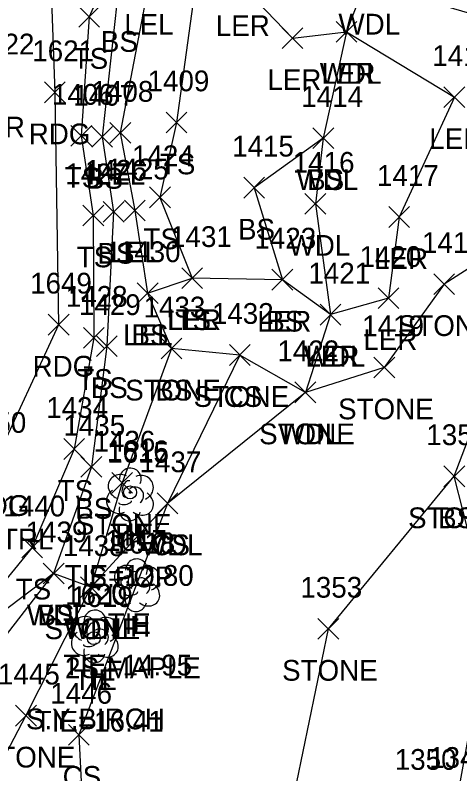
# Model space of a CAD drawing. Extents: x 1512665 to 1513714, y 110636 to 112816.
# Drawn here: x 1513122.1 to 1513164.9, y 110778.5 to 110851.6 of the extents above; entities that cross this region are included whole.
import ezdxf

# ---------------------------------------------------------------- set-up
doc = ezdxf.new("R2010")
doc.units = 0
for name, color, linetype in [('C_A', 7, 'Continuous'), ('C_C', 7, 'Continuous'), ('C_I', 7, 'Continuous'), ('CBP', 7, 'Continuous'), ('L_A', 7, 'Continuous'), ('L_C', 7, 'Continuous'), ('L_I', 7, 'Continuous'), ('L_TIC', 7, 'Continuous'), ('LARO', 7, 'Continuous'), ('LASF', 7, 'Continuous'), ('LAWA', 7, 'Continuous'), ('LELB', 7, 'Continuous'), ('LTD', 7, 'Continuous'), ('P_A', 7, 'Continuous'), ('P_I', 7, 'Continuous'), ('P_TIC', 7, 'Continuous'), ('PEU', 7, 'Continuous')]:
    doc.layers.add(name, color=color, linetype=linetype)

msp = doc.modelspace()

# ---------------------------------------------------------------- linework, layer by layer
at = {"layer": 'CBP'}
for centre, radius in [((1513133.156, 110805.643), 0.625), ((1513133.156, 110805.643), 0.0833), ((1513132.916, 110797.007), 0.625), ((1513132.916, 110797.007), 0.0833), ((1513129.651, 110791.603), 0.625), ((1513129.651, 110791.603), 0.0833)]:
    msp.add_circle(centre, radius, dxfattribs=at)
at = {"layer": 'L_TIC'}
for points in [[(1513128.213, 110850.444), (1513130.213, 110852.444)], [(1513130.213, 110850.444), (1513128.213, 110852.444)], [(1513153.003, 110848.999), (1513155.003, 110850.999)], [(1513155.003, 110848.999), (1513153.003, 110850.999)], [(1513153.003, 110848.999), (1513155.003, 110850.999)], [(1513155.003, 110848.999), (1513153.003, 110850.999)], [(1513147.788, 110848.402), (1513149.788, 110850.402)], [(1513149.788, 110848.402), (1513147.788, 110850.402)], [(1513163.386, 110842.715), (1513165.386, 110844.715)], [(1513165.386, 110842.715), (1513163.386, 110844.715)], [(1513136.613, 110840.281), (1513138.613, 110842.281)], [(1513138.613, 110840.281), (1513136.613, 110842.281)], [(1513127.452, 110838.982), (1513129.452, 110840.982)], [(1513129.452, 110838.982), (1513127.452, 110840.982)], [(1513129.46, 110838.891), (1513131.46, 110840.891)], [(1513131.46, 110838.891), (1513129.46, 110840.891)], [(1513131.21, 110839.272), (1513133.21, 110841.272)], [(1513133.21, 110839.272), (1513131.21, 110841.272)], [(1513150.762, 110838.769), (1513152.762, 110840.769)], [(1513152.762, 110838.769), (1513150.762, 110840.769)], [(1513150.762, 110838.769), (1513152.762, 110840.769)], [(1513152.762, 110838.769), (1513150.762, 110840.769)], [(1513144.105, 110833.992), (1513146.105, 110835.992)], [(1513146.105, 110833.992), (1513144.105, 110835.992)], [(1513135.029, 110833.064), (1513137.029, 110835.064)], [(1513137.029, 110833.064), (1513135.029, 110835.064)], [(1513149.998, 110832.435), (1513151.998, 110834.435)], [(1513151.998, 110832.435), (1513149.998, 110834.435)], [(1513130.567, 110831.675), (1513132.567, 110833.675)], [(1513132.567, 110831.675), (1513130.567, 110833.675)], [(1513132.616, 110831.794), (1513134.616, 110833.794)], [(1513134.616, 110831.794), (1513132.616, 110833.794)], [(1513128.607, 110831.324), (1513130.607, 110833.324)], [(1513130.607, 110831.324), (1513128.607, 110833.324)], [(1513158.063, 110831.169), (1513160.063, 110833.169)], [(1513160.063, 110831.169), (1513158.063, 110833.169)], [(1513138.129, 110825.282), (1513140.129, 110827.282)], [(1513140.129, 110825.282), (1513138.129, 110827.282)], [(1513138.129, 110825.282), (1513140.129, 110827.282)], [(1513140.129, 110825.282), (1513138.129, 110827.282)], [(1513138.129, 110825.282), (1513140.129, 110827.282)], [(1513140.129, 110825.282), (1513138.129, 110827.282)], [(1513146.819, 110825.13), (1513148.819, 110827.13)], [(1513148.819, 110825.13), (1513146.819, 110827.13)], [(1513146.819, 110825.13), (1513148.819, 110827.13)], [(1513148.819, 110825.13), (1513146.819, 110827.13)], [(1513162.393, 110824.709), (1513164.393, 110826.709)], [(1513164.393, 110824.709), (1513162.393, 110826.709)], [(1513133.843, 110823.823), (1513135.843, 110825.823)], [(1513135.843, 110823.823), (1513133.843, 110825.823)], [(1513133.843, 110823.823), (1513135.843, 110825.823)], [(1513135.843, 110823.823), (1513133.843, 110825.823)], [(1513157.033, 110823.358), (1513159.033, 110825.358)], [(1513159.033, 110823.358), (1513157.033, 110825.358)], [(1513151.454, 110821.764), (1513153.454, 110823.764)], [(1513153.454, 110821.764), (1513151.454, 110823.764)], [(1513151.454, 110821.764), (1513153.454, 110823.764)], [(1513153.454, 110821.764), (1513151.454, 110823.764)], [(1513128.65, 110819.521), (1513130.65, 110821.521)], [(1513130.65, 110819.521), (1513128.65, 110821.521)], [(1513129.921, 110818.726), (1513131.921, 110820.726)], [(1513131.921, 110818.726), (1513129.921, 110820.726)], [(1513136.14, 110818.494), (1513138.14, 110820.494)], [(1513138.14, 110818.494), (1513136.14, 110820.494)], [(1513136.14, 110818.494), (1513138.14, 110820.494)], [(1513138.14, 110818.494), (1513136.14, 110820.494)], [(1513142.722, 110817.877), (1513144.722, 110819.877)], [(1513144.722, 110817.877), (1513142.722, 110819.877)], [(1513142.722, 110817.877), (1513144.722, 110819.877)], [(1513144.722, 110817.877), (1513142.722, 110819.877)], [(1513156.638, 110816.684), (1513158.638, 110818.684)], [(1513158.638, 110816.684), (1513156.638, 110818.684)], [(1513149.034, 110814.279), (1513151.034, 110816.279)], [(1513151.034, 110814.279), (1513149.034, 110816.279)], [(1513149.034, 110814.279), (1513151.034, 110816.279)], [(1513151.034, 110814.279), (1513149.034, 110816.279)], [(1513126.768, 110808.822), (1513128.768, 110810.822)], [(1513128.768, 110808.822), (1513126.768, 110810.822)], [(1513128.422, 110807.1), (1513130.422, 110809.1)], [(1513130.422, 110807.1), (1513128.422, 110809.1)], [(1513163.38, 110806.195), (1513165.38, 110808.195)], [(1513165.38, 110806.195), (1513163.38, 110808.195)], [(1513163.38, 110806.195), (1513165.38, 110808.195)], [(1513165.38, 110806.195), (1513163.38, 110808.195)], [(1513131.379, 110805.573), (1513133.379, 110807.573)], [(1513133.379, 110805.573), (1513131.379, 110807.573)], [(1513135.759, 110803.589), (1513137.759, 110805.589)], [(1513137.759, 110803.589), (1513135.759, 110805.589)], [(1513135.759, 110803.589), (1513137.759, 110805.589)], [(1513137.759, 110803.589), (1513135.759, 110805.589)], [(1513122.727, 110799.329), (1513124.727, 110801.329)], [(1513124.727, 110799.329), (1513122.727, 110801.329)], [(1513124.79, 110796.836), (1513126.79, 110798.836)], [(1513126.79, 110796.836), (1513124.79, 110798.836)], [(1513124.79, 110796.836), (1513126.79, 110798.836)], [(1513126.79, 110796.836), (1513124.79, 110798.836)], [(1513128.365, 110795.508), (1513130.365, 110797.508)], [(1513130.365, 110795.508), (1513128.365, 110797.508)], [(1513128.365, 110795.508), (1513130.365, 110797.508)], [(1513130.365, 110795.508), (1513128.365, 110797.508)], [(1513151.248, 110791.504), (1513153.248, 110793.504)], [(1513153.248, 110791.504), (1513151.248, 110793.504)], [(1513122.124, 110783.141), (1513124.124, 110785.141)], [(1513124.124, 110783.141), (1513122.124, 110785.141)], [(1513127.216, 110781.287), (1513129.216, 110783.287)], [(1513129.216, 110781.287), (1513127.216, 110783.287)]]:
    msp.add_lwpolyline(points, dxfattribs=at)
at = {"layer": 'LARO'}
for points in [[(1513140.1, 110879.963), (1513139.267, 110874.032), (1513139.714, 110865.221), (1513139.746, 110856.646), (1513134.95, 110854.724), (1513132.21, 110840.272), (1513133.616, 110832.794), (1513134.843, 110824.823), (1513139.129, 110826.282)], [(1513142.127, 110879.225), (1513142.558, 110874.446), (1513142.308, 110866.107), (1513143.826, 110854.603), (1513148.788, 110849.402), (1513154.003, 110849.999), (1513164.386, 110843.715), (1513159.063, 110832.169), (1513158.033, 110824.358), (1513152.454, 110822.764), (1513147.819, 110826.13), (1513139.129, 110826.282)]]:
    msp.add_lwpolyline(points, dxfattribs=at)
at = {"layer": 'LASF'}
msp.add_lwpolyline([(1513155.27, 110725.127), (1513152.549, 110754.364), (1513148, 110771.81), (1513152.248, 110792.504), (1513164.38, 110807.195), (1513174.006, 110832.485), (1513163.393, 110825.709), (1513157.638, 110817.684), (1513150.034, 110815.279), (1513143.722, 110818.877), (1513137.14, 110819.494), (1513132.379, 110806.573), (1513129.365, 110796.508), (1513123.124, 110784.141), (1513118.146, 110774.685), (1513122.72, 110764.726), (1513123.65, 110752.311), (1513122.832, 110742.42), (1513125.739, 110723.519), (1513127.355, 110710.167)], dxfattribs=at)
at = {"layer": 'LAWA'}
msp.add_lwpolyline([(1513169.909, 110850.574), (1513155.8, 110854.743), (1513154.003, 110849.999), (1513151.762, 110839.769), (1513150.998, 110833.435), (1513152.454, 110822.764), (1513150.034, 110815.279), (1513136.759, 110804.589), (1513129.365, 110796.508), (1513125.79, 110797.836), (1513115.011, 110789.722), (1513110.226, 110788.604), (1513101.86, 110785.924), (1513106.089, 110777.421), (1513109.383, 110771.51), (1513113.636, 110761.19), (1513120.116, 110747.897), (1513117.812, 110736.666), (1513111.118, 110720.921), (1513118.271, 110709.907)], dxfattribs=at)
at = {"layer": 'LELB'}
for points in [[(1513137.337, 110882.904), (1513136.042, 110877.657), (1513136.12, 110864.188), (1513131.893, 110853.079), (1513130.46, 110839.891), (1513131.567, 110832.675), (1513130.921, 110819.726), (1513129.422, 110808.1), (1513125.79, 110797.836), (1513116.71, 110786.148), (1513110.55, 110779.591), (1513106.089, 110777.421)], [(1513136.07, 110882.644), (1513133.23, 110875.829), (1513134.591, 110863.608), (1513129.213, 110851.444), (1513128.452, 110839.982), (1513129.607, 110832.324), (1513129.65, 110820.521), (1513127.768, 110809.822), (1513123.727, 110800.329), (1513115.011, 110789.722)], [(1513139.746, 110856.646), (1513137.613, 110841.281), (1513136.029, 110834.064), (1513139.129, 110826.282)], [(1513151.762, 110839.769), (1513145.105, 110834.992), (1513147.819, 110826.13)], [(1513134.843, 110824.823), (1513137.14, 110819.494)], [(1513143.722, 110818.877), (1513136.759, 110804.589), (1513128.216, 110782.287), (1513129.051, 110765.488), (1513132.796, 110753.072), (1513136.854, 110749.568), (1513134.76, 110727.497), (1513135.121, 110712.795)], [(1513174.023, 110768.969), (1513164.656, 110776.108), (1513167.83, 110793.603), (1513164.38, 110807.195)]]:
    msp.add_lwpolyline(points, dxfattribs=at)
at = {"layer": 'LTD'}
for p, q in [((1513133.125, 110805.502), (1513133.125, 110805.502)), ((1513133.125, 110805.502), (1513133.125, 110805.502)), ((1513133.725, 110796.749), (1513133.725, 110796.749)), ((1513133.725, 110796.749), (1513133.725, 110796.749)), ((1513129.732, 110791.826), (1513129.732, 110791.826)), ((1513129.732, 110791.826), (1513129.732, 110791.826))]:
    msp.add_line(p, q, dxfattribs=at)
for centre in [(1513133.172, 110806.936), (1513133.772, 110798.183), (1513129.779, 110793.26)]:
    msp.add_arc(centre, 1.047, 335.52715, 180.95627, dxfattribs=at)
for centre, major_axis, ratio, start_param, end_param in [((1513132.333, 110806.168), (1.21, -0.512), 0.895232, 1.570796, 4.712389), ((1513134.167, 110806.085), (-1.141, -0.483), 0.949671, 1.570796, 4.712389), ((1513132.917, 110805.96), (-0.208, -0.792), 0.645439, 3.141593, 6.283185), ((1513132.042, 110804.793), (0.584, -1.042), 0.959034, 3.141593, 6.283185), ((1513133.625, 110805.335), (-0.5, 0.667), 0.989748, 3.141593, 6.283185), ((1513134.125, 110804.669), (-1.09, 0.792), 0.841452, 1.570796, 4.712389), ((1513133.125, 110804.002), (0.265, 1.061), 0.942809, 1.570796, 4.712389), ((1513132.667, 110804.752), (-0.625, -0.083), 0.423636, 0, 3.141593), ((1513132.933, 110797.415), (1.21, -0.512), 0.895232, 1.570796, 4.712389), ((1513134.767, 110797.332), (-1.141, -0.483), 0.949671, 1.570796, 4.712389), ((1513133.517, 110797.207), (-0.208, -0.792), 0.645439, 3.141593, 6.283185), ((1513132.642, 110796.04), (0.584, -1.042), 0.959034, 3.141593, 6.283185), ((1513134.225, 110796.582), (-0.5, 0.667), 0.989748, 3.141593, 6.283185), ((1513134.725, 110795.916), (-1.09, 0.792), 0.841452, 1.570796, 4.712389), ((1513133.267, 110795.999), (-0.625, -0.083), 0.423636, 0, 3.141593), ((1513133.725, 110795.249), (0.265, 1.061), 0.942809, 1.570796, 4.712389), ((1513128.94, 110792.493), (1.21, -0.512), 0.895232, 1.570796, 4.712389), ((1513129.524, 110792.284), (-0.208, -0.792), 0.645439, 3.141593, 6.283185), ((1513130.774, 110792.41), (-1.141, -0.483), 0.949671, 1.570796, 4.712389), ((1513130.232, 110791.66), (-0.5, 0.667), 0.989748, 3.141593, 6.283185), ((1513128.649, 110791.118), (0.584, -1.042), 0.959034, 3.141593, 6.283185), ((1513130.732, 110790.993), (-1.09, 0.792), 0.841452, 1.570796, 4.712389), ((1513129.274, 110791.076), (-0.625, -0.083), 0.423636, 0, 3.141593), ((1513129.732, 110790.326), (0.265, 1.061), 0.942809, 1.570796, 4.712389)]:
    msp.add_ellipse(centre, major_axis=major_axis, ratio=ratio, start_param=start_param, end_param=end_param, dxfattribs=at)
at = {"layer": 'P_TIC'}
for points in [[(1513124.902, 110843.176), (1513126.902, 110845.176)], [(1513126.902, 110843.176), (1513124.902, 110845.176)], [(1513125.27, 110820.797), (1513127.27, 110822.797)], [(1513127.27, 110820.797), (1513125.27, 110822.797)]]:
    msp.add_lwpolyline(points, dxfattribs=at)
at = {"layer": 'PEU'}
msp.add_lwpolyline([(1513170.256, 110966.545), (1513161.211, 110960.303), (1513151.369, 110951.546), (1513143.018, 110943.811), (1513133.251, 110931.043), (1513127.426, 110919.762), (1513124.626, 110897.943), (1513124.876, 110872.667), (1513125.902, 110844.176), (1513126.27, 110821.797), (1513120.028, 110808.377), (1513110.828, 110798.027), (1513092.487, 110788.311), (1513089.551, 110792.994), (1513086.517, 110797.2)], dxfattribs=at)

# ---------------------------------------------------------------- texts
at = {"layer": 'C_A'}
for s, p in [('HVCTRL', (1513115.067, 110800.146)), ('HVCTRL', (1513115.067, 110800.146)), ('HVCTRL', (1513115.067, 110800.146)), ('HVCTRL', (1513115.067, 110800.146)), ('TIE', (1513131.235, 110800.643)), ('TIE', (1513130.995, 110792.007)), ('TIE', (1513127.729, 110786.603))]:
    msp.add_text(s, height=2, dxfattribs=at).set_placement(p)
at = {"layer": 'C_C'}
for s, p in [('TIE=12.80', (1513126.865, 110796.643)), ('TIE=14.95', (1513126.712, 110788.007)), ('TIE=16.41', (1513123.966, 110782.603))]:
    msp.add_text(s, height=2, dxfattribs=at).set_placement(p)
at = {"layer": 'C_I'}
for s, p in [('1616', (1513130.928, 110808.643)), ('1617', (1513130.743, 110800.007)), ('1619', (1513127.47, 110794.603))]:
    msp.add_text(s, height=2, dxfattribs=at).set_placement(p)
at = {"layer": 'L_A'}
for s, p in [('LEL', (1513132.588, 110849.724)), ('WDL', (1513153.217, 110849.743)), ('LER', (1513141.409, 110849.603)), ('BS', (1513130.334, 110848.079)), ('TS', (1513127.623, 110846.444)), ('WDL', (1513151.42, 110844.999)), ('LER', (1513151.586, 110844.999)), ('LER', (1513146.371, 110844.402)), ('LER', (1513161.968, 110838.715)), ('TS', (1513136.023, 110836.281)), ('TS', (1513126.862, 110834.982)), ('LEL', (1513129.848, 110835.272)), ('BS', (1513128.901, 110834.891)), ('WDL', (1513149.179, 110834.769)), ('BS', (1513150.203, 110834.769)), ('BS', (1513143.546, 110829.992)), ('TS', (1513134.439, 110829.064)), ('WDL', (1513148.415, 110828.435)), ('BS', (1513130.008, 110827.675)), ('LEL', (1513131.254, 110827.794)), ('TS', (1513128.016, 110827.324)), ('LER', (1513156.646, 110827.169)), ('LER', (1513136.711, 110821.282)), ('LEL', (1513136.766, 110821.282)), ('TS', (1513137.538, 110821.282)), ('LER', (1513145.402, 110821.13)), ('BS', (1513146.26, 110821.13)), ('STONE', (1513158.937, 110820.709)), ('LEL', (1513132.481, 110819.823)), ('BS', (1513133.284, 110819.823)), ('LER', (1513155.615, 110819.358)), ('WDL', (1513149.871, 110817.764)), ('LER', (1513150.036, 110817.764)), ('TS', (1513128.06, 110815.521)), ('BS', (1513129.362, 110814.726)), ('STONE', (1513132.684, 110814.494)), ('BS', (1513135.581, 110814.494)), ('STONE', (1513139.266, 110813.877)), ('CS', (1513142.163, 110813.877)), ('STONE', (1513153.182, 110812.684)), ('STONE', (1513145.577, 110810.279)), ('WDL', (1513147.451, 110810.279)), ('TS', (1513126.177, 110804.822)), ('BS', (1513127.863, 110803.1)), ('STONE', (1513159.923, 110802.195)), ('BS', (1513162.821, 110802.195)), ('STONE', (1513127.922, 110801.573)), ('H', (1513132.558, 110800.502)), ('WDL', (1513134.176, 110799.589)), ('CS', (1513135.2, 110799.589)), ('TS', (1513122.136, 110795.329)), ('WDL', (1513123.208, 110792.836)), ('BS', (1513124.231, 110792.836)), ('STONE', (1513124.909, 110791.508)), ('WDL', (1513126.783, 110791.508)), ('H', (1513133.158, 110791.749)), ('STONE', (1513147.791, 110787.504)), ('H', (1513129.165, 110786.826)), ('STONE', (1513118.667, 110779.141)), ('CS', (1513126.657, 110777.287))]:
    msp.add_text(s, height=2, dxfattribs=at).set_placement(p)
at = {"layer": 'L_C'}
for s, p in [('S.POP', (1513129.149, 110796.502)), ('2S.MAPLE', (1513126.89, 110787.749)), ('S.Y.BIRCH', (1513123.118, 110782.826))]:
    msp.add_text(s, height=2, dxfattribs=at).set_placement(p)
at = {"layer": 'L_I'}
for s, p in [('1413', (1513162.26, 110846.715)), ('1409', (1513134.834, 110844.281)), ('1408', (1513129.439, 110843.272)), ('1406', (1513125.625, 110842.982)), ('1407', (1513127.688, 110842.891)), ('1414', (1513149.636, 110842.769)), ('1414', (1513149.636, 110842.769)), ('1415', (1513142.979, 110837.992)), ('1424', (1513133.336, 110837.064)), ('1416', (1513148.817, 110836.435)), ('1425', (1513130.924, 110835.794)), ('1427', (1513126.914, 110835.324)), ('1426', (1513128.819, 110835.675)), ('1417', (1513156.937, 110835.169)), ('1431', (1513137.003, 110829.282)), ('1431', (1513137.003, 110829.282)), ('1431', (1513137.003, 110829.282)), ('1423', (1513145.126, 110829.13)), ('1423', (1513145.126, 110829.13)), ('1418', (1513161.267, 110828.709)), ('1430', (1513132.063, 110827.823)), ('1430', (1513132.063, 110827.823)), ('1420', (1513155.253, 110827.358)), ('1421', (1513150.328, 110825.764)), ('1421', (1513150.328, 110825.764)), ('1428', (1513126.957, 110823.521)), ('1429', (1513128.221, 110822.726)), ('1433', (1513134.448, 110822.494)), ('1433', (1513134.448, 110822.494)), ('1432', (1513141.03, 110821.877)), ('1432', (1513141.03, 110821.877)), ('1419', (1513155.504, 110820.684)), ('1422', (1513147.341, 110818.279)), ('1422', (1513147.341, 110818.279)), ('1434', (1513125.075, 110812.822)), ('1435', (1513126.729, 110811.1)), ('1354', (1513161.687, 110810.195)), ('1354', (1513161.687, 110810.195)), ('1436', (1513129.631, 110809.573)), ('1615', (1513130.952, 110808.502)), ('1437', (1513134.066, 110807.589)), ('1437', (1513134.066, 110807.589)), ('1440', (1513120.947, 110803.329)), ('1439', (1513123.089, 110800.836)), ('1439', (1513123.089, 110800.836)), ('1438', (1513126.672, 110799.508)), ('1438', (1513126.672, 110799.508)), ('1618', (1513131.552, 110799.749)), ('1353', (1513149.555, 110795.504)), ('1620', (1513126.905, 110794.826)), ('1445', (1513120.431, 110787.141)), ('1446', (1513125.468, 110785.287)), ('1350', (1513158.645, 110778.921)), ('1349', (1513161.955, 110779.108))]:
    msp.add_text(s, height=2, dxfattribs=at).set_placement(p)
at = {"layer": 'P_A'}
for s, p in [('CR', (1513119.159, 110839.828)), ('RDG', (1513123.39, 110839.176)), ('RDG', (1513123.758, 110816.797)), ('RDG', (1513117.516, 110803.377))]:
    msp.add_text(s, height=2, dxfattribs=at).set_placement(p)
at = {"layer": 'P_I'}
for s, p in [('1622', (1513117.986, 110847.828)), ('1621', (1513123.729, 110847.176)), ('1649', (1513123.522, 110824.797)), ('1650', (1513117.201, 110811.377))]:
    msp.add_text(s, height=2, dxfattribs=at).set_placement(p)

doc.saveas('drawing.dxf')
